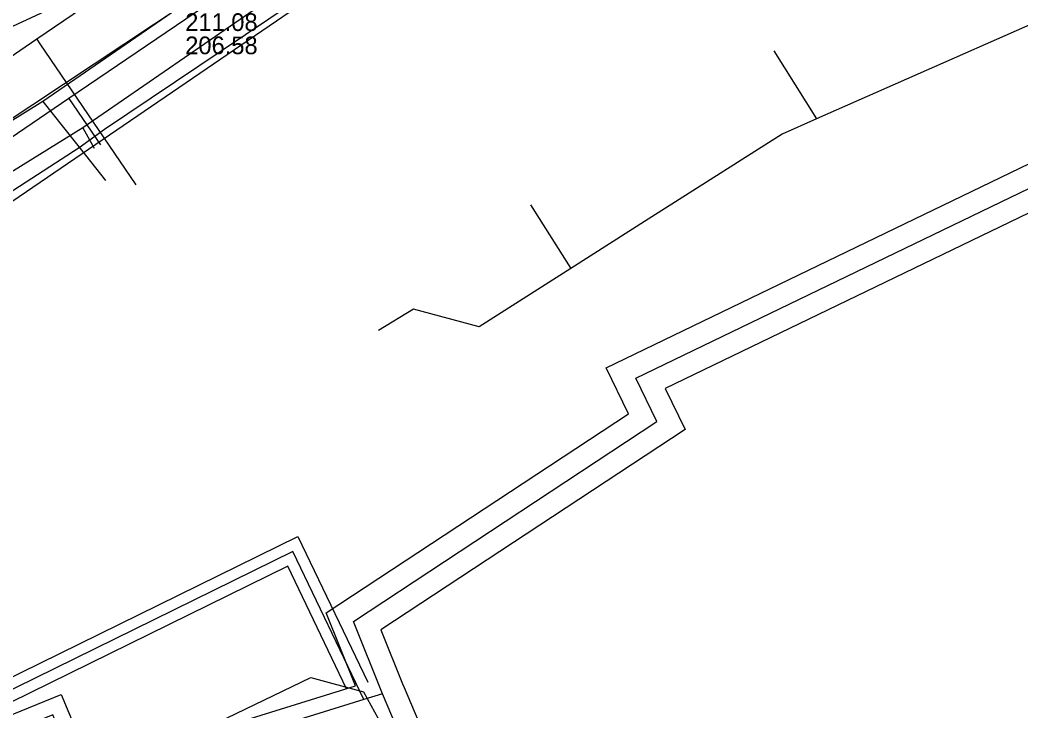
# Model space of a CAD drawing. Extents: x -600309 to -598967, y -1161267 to -1160292.
# Drawn here: x -599534.69 to -599489.45, y -1161198.61 to -1161167.37 of the extents above; entities that cross this region are included whole.
import ezdxf

# ---------------------------------------------------------------- set-up
doc = ezdxf.new("R2010")
doc.units = 0
for name, color, linetype in [('Vrstva 12', 7, 'Continuous'), ('Vrstva 13', 7, 'Continuous'), ('Vrstva 16', 7, 'Continuous'), ('Vrstva 37', 7, 'Continuous'), ('Vrstva 38', 7, 'Continuous'), ('Vrstva 42', 7, 'Continuous'), ('Vrstva 55', 7, 'Continuous'), ('Vrstva 58', 7, 'Continuous'), ('Vrstva 9', 7, 'Continuous')]:
    doc.layers.add(name, color=color, linetype=linetype)

msp = doc.modelspace()

# ---------------------------------------------------------------- linework, layer by layer
at = {"layer": 'Vrstva 12'}
msp.add_line((-599531.74, -1161173.48), (-599530.831, -1161174.621), dxfattribs=at)
msp.add_line((-599531.74, -1161173.48), (-599530.831, -1161174.621), dxfattribs=at)
for points in [[(-599513.31, -1161157.36), (-599514.8, -1161158.38), (-599542.4, -1161176.7), (-599550.4, -1161181.13), (-599580.66, -1161192.82)], [(-599518.21, -1161160.4), (-599522.78, -1161163.55), (-599532.21, -1161170.06)], [(-599484.33, -1161165.5), (-599498.69, -1161171.84)], [(-599500.62, -1161168.77), (-599498.69, -1161171.84)], [(-599532.21, -1161170.06), (-599533.66, -1161171.05)], [(-599533.66, -1161171.05), (-599543.7, -1161177.29), (-599551.8, -1161181.57), (-599564.18, -1161186.71), (-599565.3, -1161187.97), (-599574.8, -1161191.62), (-599583.47, -1161194.61), (-599584.26, -1161194.68), (-599587.79, -1161195.63)], [(-599533.66, -1161171.05), (-599531.74, -1161173.48)], [(-599498.69, -1161171.84), (-599500.24, -1161172.53), (-599506.3, -1161176.38)], [(-599511.61, -1161175.73), (-599509.8, -1161178.61)], [(-599506.3, -1161176.38), (-599509.8, -1161178.61)], [(-599509.8, -1161178.61), (-599513.93, -1161181.24), (-599516.9, -1161180.44), (-599518.49, -1161181.41)]]:
    msp.add_lwpolyline(points, dxfattribs=at)
at = {"layer": 'Vrstva 13'}
for points in [[(-599411.725, -1161101.732), (-599414.519, -1161102.315), (-599450.573, -1161109.837), (-599460.653, -1161116.976), (-599462.737, -1161118.461), (-599483.111, -1161132.905), (-599490.491, -1161138.137), (-599508.933, -1161151.212), (-599509.583, -1161151.672), (-599510.091, -1161152.018), (-599523.741, -1161161.304), (-599533.935, -1161168.24), (-599537.024, -1161170.341), (-599537.86, -1161170.91)], [(-599533.935, -1161168.24), (-599533.794, -1161168.447), (-599529.46, -1161174.818)]]:
    msp.add_lwpolyline(points, dxfattribs=at)
at = {"layer": 'Vrstva 16'}
for points in [[(-599362.74, -1161135.03), (-599363.49, -1161135.7), (-599365.97, -1161134.6), (-599372.85, -1161131.57), (-599390.62, -1161123.28), (-599395.67, -1161110.31), (-599395.85, -1161109.84), (-599431.51, -1161116.63), (-599437.98, -1161113.92), (-599446.12, -1161118), (-599467.25, -1161128.61), (-599480.16, -1161135.09), (-599482.54, -1161136.74), (-599491.58, -1161143), (-599506.15, -1161153.54), (-599506.77, -1161153.95), (-599507.46, -1161154.42), (-599517.51, -1161160.75), (-599532.48, -1161170.92), (-599540.46, -1161176.34), (-599543.07, -1161174.85), (-599544.186, -1161175.34), (-599546.53, -1161176.37)], [(-599532.48, -1161170.92), (-599531.06, -1161173.01)]]:
    msp.add_lwpolyline(points, dxfattribs=at)
at = {"layer": 'Vrstva 37'}
for points in [[(-599518.301, -1161197.832), (-599519.623, -1161194.559), (-599505.912, -1161185.528), (-599506.86, -1161183.564), (-599485.599, -1161173.305), (-599457.587, -1161162.472), (-599460.116, -1161156.749), (-599443.169, -1161149.329)], [(-599519.147, -1161198.094), (-599522.361, -1161191.397), (-599536.715, -1161198.447), (-599554.678, -1161162.517)], [(-599518.301, -1161197.832), (-599519.147, -1161198.094), (-599531.852, -1161202.037), (-599533.206, -1161198.785), (-599577.45, -1161216.847)], [(-599477.949, -1161252.74), (-599487.295, -1161230.74), (-599501.767, -1161236.872), (-599518.301, -1161197.832)]]:
    msp.add_lwpolyline(points, dxfattribs=at)
at = {"layer": 'Vrstva 38'}
for points in [[(-599519.523, -1161197.478), (-599520.857, -1161194.174), (-599507.193, -1161185.174), (-599508.195, -1161183.098), (-599485.997, -1161172.387), (-599458.925, -1161161.917), (-599461.436, -1161156.235), (-599444.488, -1161148.815)], [(-599443.68, -1161150.645), (-599458.796, -1161157.263), (-599456.249, -1161163.027), (-599485.201, -1161174.223), (-599505.525, -1161184.03), (-599504.631, -1161185.882), (-599518.389, -1161194.944), (-599517.374, -1161197.457)], [(-599554.23, -1161162.294), (-599536.49, -1161197.779), (-599522.128, -1161190.726), (-599518.97, -1161197.306)], [(-599519.936, -1161197.606), (-599522.593, -1161192.068), (-599536.941, -1161199.114), (-599555.125, -1161162.741)], [(-599577.714, -1161216.199), (-599532.827, -1161197.874), (-599531.451, -1161201.18), (-599519.523, -1161197.478)], [(-599517.38, -1161197.442), (-599501.236, -1161235.561), (-599486.765, -1161229.43), (-599477.434, -1161251.395)]]:
    msp.add_lwpolyline(points, dxfattribs=at)
at = {"layer": 'Vrstva 42'}
msp.add_lwpolyline([(-599518.42, -1161163.84), (-599519, -1161164.06), (-599519.903, -1161164.938), (-599519.727, -1161165.191), (-599519.891, -1161165.305), (-599520.055, -1161165.419), (-599520.233, -1161165.163), (-599530.87, -1161172.32), (-599532.02, -1161173.15), (-599540.074, -1161178.371)], dxfattribs=at)
at = {"layer": 'Vrstva 55'}
msp.add_lwpolyline([(-599572.08, -1161226.46), (-599572.79, -1161226.01), (-599573.1, -1161226.15), (-599574.59, -1161221.93), (-599566.29, -1161218.18), (-599547.28, -1161209.27), (-599529.58, -1161200.97), (-599521.55, -1161197.1), (-599519.16, -1161197.74), (-599518.34, -1161199.25), (-599516.89, -1161202.34), (-599517.98, -1161202.95)], dxfattribs=at)
at = {"layer": 'Vrstva 58'}
for points in [[(-599516.95, -1161161.91), (-599524.5, -1161167.19), (-599531.86, -1161172.24)], [(-599541.43, -1161179.66), (-599540.06, -1161178.99), (-599521.86, -1161166.57)], [(-599531.86, -1161172.24), (-599542.03, -1161178.55), (-599549.85, -1161182.35), (-599560.267, -1161186.822), (-599576.998, -1161193.457), (-599580.01, -1161194.54), (-599582.739, -1161195.164), (-599590.88, -1161197.47), (-599591.88, -1161197.74), (-599593.51, -1161198.15)], [(-599531.86, -1161172.24), (-599531.34, -1161173.17)]]:
    msp.add_lwpolyline(points, dxfattribs=at)
at = {"layer": 'Vrstva 9'}
msp.add_lwpolyline([(-599555.45, -1161177.23), (-599553.591, -1161176.358), (-599550.789, -1161175.044), (-599547.556, -1161173.528), (-599535.405, -1161167.829), (-599531.894, -1161166.182), (-599524.79, -1161162.85)], dxfattribs=at)

# ---------------------------------------------------------------- texts
at = {"layer": 'Vrstva 12'}
for s, p in [('211.08', (-599527.224, -1161167.869)), ('206.58', (-599527.224, -1161168.919))]:
    msp.add_text(s, height=0.8, dxfattribs=at).set_placement(p)

doc.saveas('drawing.dxf')
